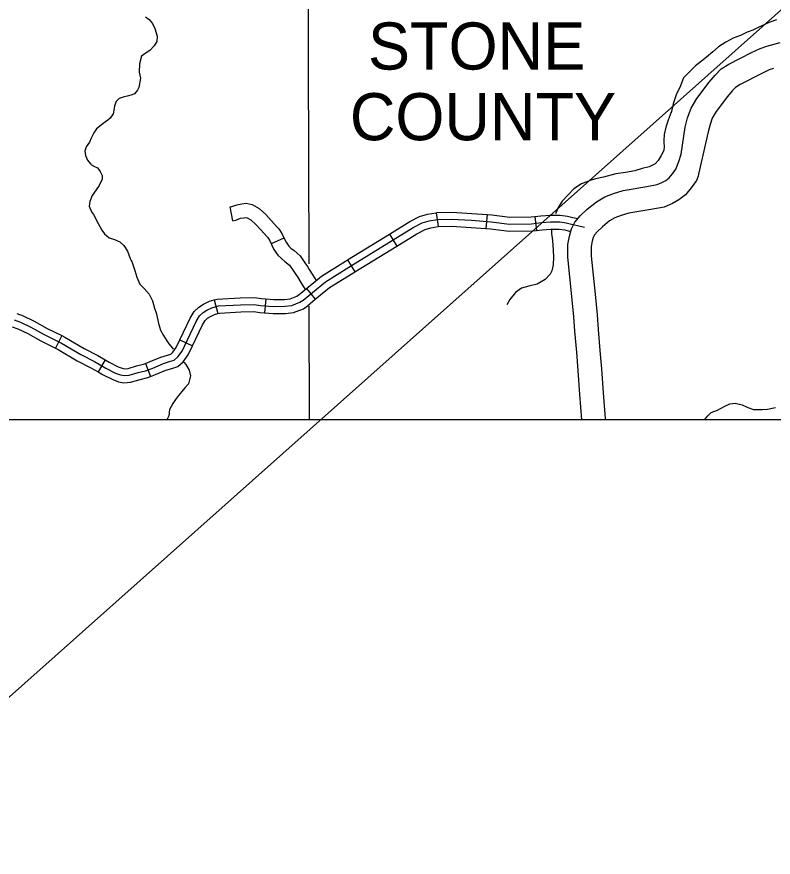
# Model space of a CAD drawing. Extents: x 1377389 to 1380723, y 1168351 to 1170484.
# Drawn here: x 1378518.7 to 1378680.8, y 1168608.3 to 1168788.5 of the extents above; entities that cross this region are included whole.
import ezdxf

# ---------------------------------------------------------------- set-up
doc = ezdxf.new("R2010")
doc.units = 0
for name, color, linetype in [('B_Contour_Elevations', 7, 'Continuous'), ('B_Fill', 7, 'Continuous'), ('B_Text', 7, 'Continuous'), ('Default', 7, 'Continuous')]:
    doc.layers.add(name, color=color, linetype=linetype)

msp = doc.modelspace()

# ---------------------------------------------------------------- linework, layer by layer
at = {"layer": 'B_Contour_Elevations'}
msp.add_line((1378478.5, 1168608.3), (1379068.4, 1169134.14), dxfattribs=at)
at = {"layer": 'B_Fill'}
for p, q in [((1378679.39, 1168782.21), (1378682.25, 1168782.99)), ((1378671.27, 1168778.34), (1378676.1, 1168780.84)), ((1378676.1, 1168780.84), (1378678, 1168781.74)), ((1378678, 1168781.74), (1378679.39, 1168782.21)), ((1378668.29, 1168776.02), (1378669.6, 1168777.34)), ((1378669.6, 1168777.34), (1378671.27, 1168778.34)), ((1378679.89, 1168777.1), (1378678.32, 1168776.36)), ((1378680.85, 1168777.43), (1378679.89, 1168777.1)), ((1378667.02, 1168774.5), (1378668.29, 1168776.02)), ((1378678.32, 1168776.36), (1378673.71, 1168773.97)), ((1378664.42, 1168771), (1378667.02, 1168774.5)), ((1378673.71, 1168773.97), (1378672.7, 1168773.37)), ((1378671.99, 1168772.65), (1378670.95, 1168771.4)), ((1378672.7, 1168773.37), (1378671.99, 1168772.65)), ((1378663.15, 1168768.9), (1378664.42, 1168771)), ((1378670.95, 1168771.4), (1378668.57, 1168768.21)), ((1378662.43, 1168766.87), (1378663.15, 1168768.9)), ((1378668.57, 1168768.21), (1378667.7, 1168766.75)), ((1378658.87, 1168767.95), (1378658.9, 1168768.07)), ((1378661.92, 1168764.84), (1378662.43, 1168766.87)), ((1378667.7, 1168766.75), (1378667.22, 1168765.42)), ((1378661.05, 1168759.03), (1378661.92, 1168764.84)), ((1378667.22, 1168765.42), (1378666.83, 1168763.85)), ((1378666.83, 1168763.85), (1378664.77, 1168754.73)), ((1378659.88, 1168755.84), (1378660.56, 1168757.49)), ((1378660.56, 1168757.49), (1378661.05, 1168759.03)), ((1378659.18, 1168754.83), (1378659.88, 1168755.84)), ((1378657.75, 1168753.44), (1378658.48, 1168753.99)), ((1378658.48, 1168753.99), (1378659.18, 1168754.83)), ((1378664.67, 1168754.34), (1378664.29, 1168753.43)), ((1378664.77, 1168754.73), (1378664.67, 1168754.34)), ((1378648.58, 1168751.28), (1378653.68, 1168752.14)), ((1378653.68, 1168752.14), (1378655.93, 1168752.53)), ((1378655.93, 1168752.53), (1378656.92, 1168752.95)), ((1378656.92, 1168752.95), (1378657.75, 1168753.44)), ((1378664.29, 1168753.43), (1378663.16, 1168751.8)), ((1378644.68, 1168749.91), (1378646.54, 1168750.61)), ((1378646.54, 1168750.61), (1378648.58, 1168751.28)), ((1378661.95, 1168750.36), (1378660.54, 1168749.27)), ((1378663.16, 1168751.8), (1378661.95, 1168750.36)), ((1378640.9, 1168747.28), (1378642.86, 1168748.85)), ((1378642.86, 1168748.85), (1378644.68, 1168749.91)), ((1378659.17, 1168748.48), (1378657.37, 1168747.7)), ((1378660.54, 1168749.27), (1378659.17, 1168748.48)), ((1378564.94, 1168744.79), (1378564.37, 1168747.74)), ((1378608.56, 1168746.49), (1378608.99, 1168743.52)), ((1378639.37, 1168745.86), (1378640.9, 1168747.28)), ((1378654.52, 1168747.21), (1378649.79, 1168746.41)), ((1378657.37, 1168747.7), (1378654.52, 1168747.21)), ((1378619.43, 1168746.11), (1378619.2, 1168743.12)), ((1378629.66, 1168745.68), (1378630.02, 1168742.7)), ((1378638.23, 1168744.47), (1378639.37, 1168745.86)), ((1378645.7, 1168744.72), (1378644.16, 1168743.49)), ((1378646.83, 1168745.38), (1378645.7, 1168744.72)), ((1378648.2, 1168745.89), (1378646.83, 1168745.38)), ((1378649.79, 1168746.41), (1378648.2, 1168745.89)), ((1378637.07, 1168741.49), (1378637.5, 1168743.03)), ((1378637.5, 1168743.03), (1378638.23, 1168744.47)), ((1378644.16, 1168743.49), (1378643.02, 1168742.42)), ((1378575.89, 1168741.07), (1378573.18, 1168739.79)), ((1378598.54, 1168741.9), (1378600.11, 1168739.34)), ((1378636.75, 1168739.67), (1378637.07, 1168741.49)), ((1378642.18, 1168741.2), (1378641.95, 1168740.38)), ((1378642.45, 1168741.73), (1378642.18, 1168741.2)), ((1378643.02, 1168742.42), (1378642.45, 1168741.73)), ((1378636.76, 1168736.93), (1378636.75, 1168739.67)), ((1378641.95, 1168740.38), (1378641.75, 1168739.25)), ((1378641.75, 1168739.25), (1378641.76, 1168737.19)), ((1378589.54, 1168736.37), (1378591.11, 1168733.81)), ((1378637.61, 1168728.52), (1378636.76, 1168736.93)), ((1378641.76, 1168737.19), (1378642.59, 1168729.03)), ((1378580.71, 1168730.23), (1378582.63, 1168727.93)), ((1378638.06, 1168724.2), (1378637.61, 1168728.52)), ((1378642.59, 1168729.03), (1378643.04, 1168724.62)), ((1378560.96, 1168727.79), (1378561.76, 1168724.89)), ((1378571.99, 1168728.02), (1378571.74, 1168725.03)), ((1378638.27, 1168721.1), (1378638.06, 1168724.2)), ((1378643.04, 1168724.62), (1378643.25, 1168721.48)), ((1378643.25, 1168721.48), (1378643.64, 1168716.98)), ((1378528.29, 1168720.16), (1378526.97, 1168717.46)), ((1378638.66, 1168716.56), (1378638.27, 1168721.1)), ((1378553.6, 1168719.25), (1378556.31, 1168717.97)), ((1378638.99, 1168712.66), (1378638.66, 1168716.56)), ((1378643.64, 1168716.98), (1378643.97, 1168713.03)), ((1378537.59, 1168714.95), (1378536.09, 1168712.35)), ((1378546.26, 1168714.19), (1378547.31, 1168711.38)), ((1378639.32, 1168707.55), (1378638.99, 1168712.66)), ((1378643.97, 1168713.03), (1378644.31, 1168707.9)), ((1378639.75, 1168702.1), (1378639.32, 1168707.55)), ((1378644.31, 1168707.9), (1378644.74, 1168702.37)), ((1378644.76, 1168702.1), (1378639.75, 1168702.1)), ((1378644.74, 1168702.37), (1378644.76, 1168702.1))]:
    msp.add_line(p, q, dxfattribs=at)
for points in [[(1378580.94, 1168836.74), (1378581.05, 1168801.57), (1378581.22, 1168735.56)], [(1378546.2, 1168788.52), (1378547, 1168787.96), (1378547.74, 1168787.08), (1378548.24, 1168786.02), (1378548.7, 1168784.32), (1378548.63, 1168783.24), (1378548.11, 1168782.28), (1378547.14, 1168781.3), (1378546.34, 1168780.8), (1378545.4, 1168780.04), (1378544.93, 1168778.4), (1378544.87, 1168776.6), (1378545.16, 1168775.38), (1378544.8, 1168773.36), (1378544.52, 1168772.78), (1378543.91, 1168771.99), (1378543.41, 1168771.75), (1378542.29, 1168771.47), (1378541.42, 1168771.27), (1378540.62, 1168770.99), (1378539.94, 1168770.33), (1378539.56, 1168769.45), (1378539.51, 1168768.83), (1378539.31, 1168767.73), (1378538.69, 1168766.77), (1378538.15, 1168766.35), (1378537.18, 1168765.65), (1378536.34, 1168765.01), (1378535.7, 1168764.45), (1378535.17, 1168763.63), (1378534.57, 1168762.48), (1378534.2, 1168761.64), (1378533.52, 1168760.62), (1378533.22, 1168759.66), (1378533.35, 1168758.78), (1378533.77, 1168757.74), (1378534.45, 1168756.96), (1378534.69, 1168756.78), (1378535.33, 1168756.42), (1378535.91, 1168756.1), (1378536.51, 1168755.36), (1378536.93, 1168754.5), (1378536.91, 1168753.7), (1378536.32, 1168752.3), (1378535.64, 1168751.38), (1378534.83, 1168750.18), (1378534.27, 1168748.9), (1378534.19, 1168747.88), (1378534.68, 1168746.66), (1378535.1, 1168746.08), (1378536.12, 1168744.18), (1378536.84, 1168742.72), (1378537.46, 1168741.94), (1378538.48, 1168741.12), (1378539.6, 1168740.78), (1378540.72, 1168740.22), (1378541.6, 1168739.46), (1378542.38, 1168738.24), (1378542.97, 1168736.66), (1378543.15, 1168736.26), (1378543.27, 1168736.02), (1378543.95, 1168734.08), (1378544.34, 1168732.68), (1378545.04, 1168731.18), (1378545.94, 1168730.24), (1378547, 1168729.02), (1378547.72, 1168727.58), (1378548.13, 1168726.06), (1378548.57, 1168724.82), (1378549.01, 1168722.76), (1378549.48, 1168721.28), (1378550.08, 1168720.2), (1378550.84, 1168719), (1378551.26, 1168718.4), (1378552, 1168717.42), (1378552.19, 1168717.22)], [(1378681.49, 1168787.89), (1378680.07, 1168787.33), (1378677.54, 1168786.24), (1378676.37, 1168785.61), (1378675.17, 1168785.18), (1378673.75, 1168784.47), (1378672.19, 1168783.89), (1378670.58, 1168783.07), (1378669.07, 1168782.05), (1378667.79, 1168781), (1378666.48, 1168779.84), (1378665.37, 1168778.96), (1378664.09, 1168777.97), (1378662.96, 1168776.85), (1378661.54, 1168775.39), (1378660.75, 1168773.36), (1378660.02, 1168771.99), (1378659.35, 1168769.88), (1378658.87, 1168767.95)], [(1378658.9, 1168768.07), (1378658.26, 1168766.37), (1378657.74, 1168764.86), (1378657.4, 1168763.29), (1378657.33, 1168761.96), (1378657.35, 1168761.53), (1378657.36, 1168760.72), (1378657.33, 1168759.81), (1378656.83, 1168758.93), (1378656.74, 1168758.8), (1378656.12, 1168757.67), (1378655.47, 1168757.01), (1378654.16, 1168756.35), (1378652.65, 1168755.96), (1378651.12, 1168755.51), (1378649.11, 1168755.14), (1378647.06, 1168754.81), (1378644.41, 1168754.14), (1378642.69, 1168753.73), (1378641.55, 1168753.39), (1378639.67, 1168752.68), (1378638.05, 1168751.65), (1378636.79, 1168750.32), (1378635.55, 1168748.94), (1378634.7, 1168747.62), (1378634.11, 1168746.27)], [(1378564.37, 1168747.74), (1378564.76, 1168747.81), (1378565.84, 1168748.22), (1378566.91, 1168748.39), (1378567.78, 1168748.51), (1378569.07, 1168748.25), (1378570.58, 1168747.43), (1378572.03, 1168746.1), (1378573.17, 1168744.86), (1378573.91, 1168744.01), (1378574.46, 1168743.4)], [(1378598.54, 1168741.9), (1378602.9, 1168744.58), (1378604.99, 1168745.68), (1378606.69, 1168746.22), (1378608.56, 1168746.49)], [(1378608.56, 1168746.49), (1378608.72, 1168746.51), (1378611.87, 1168746.58), (1378616.2, 1168746.36), (1378619.43, 1168746.11)], [(1378564.94, 1168744.79), (1378565.58, 1168744.91), (1378566.61, 1168745.31), (1378567.34, 1168745.42), (1378567.69, 1168745.47), (1378568.05, 1168745.4), (1378568.83, 1168744.97), (1378569.91, 1168743.98), (1378570.94, 1168742.85), (1378571.67, 1168742.02), (1378572.22, 1168741.4)], [(1378582.01, 1168729.4), (1378584.8, 1168731.68), (1378589.84, 1168734.83), (1378603.63, 1168743.3), (1378605.56, 1168744.32), (1378607.02, 1168744.78), (1378608.84, 1168745.04), (1378611.85, 1168745.1), (1378616.1, 1168744.89), (1378620.3, 1168744.57), (1378624.27, 1168744.07), (1378628.98, 1168744.11), (1378631.09, 1168744.37), (1378633.05, 1168744.52), (1378635.01, 1168744.52), (1378636.4, 1168744.3), (1378637.5, 1168744.02), (1378638.8, 1168743.76), (1378640.34, 1168743.38)], [(1378619.43, 1168746.11), (1378620.44, 1168746.03), (1378624.35, 1168745.54), (1378628.88, 1168745.58), (1378629.66, 1168745.68)], [(1378629.66, 1168745.68), (1378630.95, 1168745.84), (1378633, 1168745.99), (1378635.12, 1168745.99), (1378636.7, 1168745.74), (1378637.83, 1168745.45), (1378638.87, 1168745.25)], [(1378574.46, 1168743.4), (1378574.81, 1168743.01), (1378575.43, 1168742.04), (1378575.93, 1168740.99), (1378576.35, 1168740.15), (1378576.93, 1168739.35), (1378577.35, 1168738.93), (1378578.06, 1168738.37), (1378579.35, 1168737.22), (1378580.36, 1168735.77), (1378580.92, 1168734.94)], [(1378600.11, 1168739.34), (1378604.39, 1168741.97), (1378606.16, 1168742.9), (1378607.36, 1168743.29), (1378608.99, 1168743.52)], [(1378608.96, 1168743.52), (1378611.83, 1168743.58), (1378616.01, 1168743.36), (1378619.2, 1168743.12)], [(1378619.2, 1168743.12), (1378620.14, 1168743.05), (1378624.18, 1168742.54), (1378629.08, 1168742.59), (1378630.02, 1168742.7)], [(1378630.02, 1168742.7), (1378631.24, 1168742.85), (1378633.11, 1168742.99), (1378634.89, 1168742.99), (1378636.1, 1168742.8), (1378637.35, 1168742.48)], [(1378572.22, 1168741.4), (1378572.42, 1168741.19), (1378572.8, 1168740.58), (1378573.23, 1168739.68), (1378573.77, 1168738.59), (1378574.63, 1168737.4), (1378575.36, 1168736.67), (1378576.13, 1168736.07), (1378577.09, 1168735.22), (1378577.89, 1168734.07), (1378578.44, 1168733.25)], [(1378589.54, 1168736.37), (1378598.54, 1168741.9)], [(1378633.28, 1168742.77), (1378633.23, 1168742.04), (1378633.45, 1168740.52), (1378633.63, 1168738.48), (1378633.71, 1168736.99), (1378633.6, 1168735.35), (1378633.31, 1168734.01), (1378632.98, 1168733.34), (1378631.87, 1168732.15), (1378630.21, 1168731.21), (1378628.42, 1168730.78), (1378626.84, 1168730.32), (1378625.52, 1168729.36), (1378624.33, 1168727.92), (1378623.64, 1168726.77)], [(1378591.11, 1168733.81), (1378600.11, 1168739.34)], [(1378580.71, 1168730.23), (1378581.07, 1168730.53), (1378583.94, 1168732.88), (1378589.07, 1168736.08), (1378589.54, 1168736.37)], [(1378580.92, 1168734.94), (1378581.33, 1168734.35), (1378582.08, 1168733.13), (1378582.82, 1168731.96)], [(1378578.44, 1168733.25), (1378578.81, 1168732.72), (1378579.54, 1168731.54), (1378580.48, 1168730.04)], [(1378582.63, 1168727.93), (1378582.98, 1168728.22), (1378585.69, 1168730.44), (1378590.65, 1168733.53), (1378591.11, 1168733.81)], [(1378518.09, 1168723.5), (1378519.43, 1168723.04), (1378521.69, 1168721.96), (1378524.49, 1168720.38), (1378528.25, 1168718.54), (1378532.36, 1168716.1), (1378535.28, 1168714.58), (1378537.74, 1168713.17), (1378539.82, 1168712.11), (1378540.86, 1168711.73), (1378541.7, 1168711.57), (1378542.76, 1168711.65), (1378544.69, 1168712.23), (1378546.25, 1168712.61), (1378547.8, 1168713.19), (1378550.06, 1168714.13), (1378551.41, 1168714.57), (1378552.37, 1168714.9), (1378553.15, 1168715.56), (1378554.08, 1168716.82), (1378557.08, 1168723.18), (1378557.83, 1168724.36), (1378558.59, 1168725.08), (1378559.39, 1168725.6), (1378560.48, 1168726.12), (1378561.86, 1168726.51), (1378566.57, 1168726.75), (1378569.52, 1168726.85), (1378570.9, 1168726.63), (1378573.62, 1168726.41), (1378576.13, 1168726.43), (1378577.59, 1168726.62), (1378579.34, 1168727.28), (1378580.04, 1168727.76), (1378582.01, 1168729.4)], [(1378571.99, 1168728.02), (1378573.67, 1168727.89), (1378576.03, 1168727.91), (1378577.23, 1168728.05), (1378578.65, 1168728.59), (1378579.15, 1168728.93), (1378580.71, 1168730.23)], [(1378553.6, 1168719.25), (1378555.79, 1168723.89), (1378556.69, 1168725.31), (1378557.67, 1168726.24), (1378558.66, 1168726.89), (1378559.97, 1168727.51), (1378560.96, 1168727.79)], [(1378560.96, 1168727.79), (1378561.62, 1168727.97), (1378566.51, 1168728.22), (1378569.61, 1168728.33), (1378571.08, 1168728.09), (1378571.99, 1168728.02)], [(1378571.74, 1168725.03), (1378573.56, 1168724.88), (1378576.23, 1168724.91), (1378577.96, 1168725.12), (1378580.06, 1168725.91), (1378580.96, 1168726.54), (1378582.63, 1168727.93)], [(1378518.65, 1168724.86), (1378519.99, 1168724.4), (1378522.37, 1168723.27), (1378525.17, 1168721.68), (1378528.29, 1168720.16)], [(1378556.31, 1168717.97), (1378558.42, 1168722.44), (1378559.02, 1168723.38), (1378559.54, 1168723.88), (1378560.13, 1168724.27), (1378561.02, 1168724.69), (1378561.76, 1168724.89)], [(1378561.76, 1168724.89), (1378562.1, 1168724.99), (1378566.63, 1168725.22), (1378569.43, 1168725.32), (1378570.72, 1168725.11), (1378571.74, 1168725.03)], [(1378581.25, 1168726.47), (1378581.31, 1168702.1)], [(1378517.68, 1168722.02), (1378518.85, 1168721.62), (1378520.98, 1168720.6), (1378523.78, 1168719.03), (1378526.97, 1168717.46)], [(1378528.29, 1168720.16), (1378528.95, 1168719.84), (1378533.08, 1168717.39), (1378535.99, 1168715.88), (1378537.59, 1168714.95)], [(1378546.26, 1168714.19), (1378547.26, 1168714.56), (1378549.54, 1168715.51), (1378550.95, 1168715.97), (1378551.63, 1168716.2), (1378552.06, 1168716.57), (1378552.81, 1168717.58), (1378553.6, 1168719.25)], [(1378547.31, 1168711.38), (1378548.36, 1168711.77), (1378550.59, 1168712.7), (1378551.89, 1168713.12), (1378553.13, 1168713.54), (1378554.27, 1168714.51), (1378555.4, 1168716.03), (1378556.31, 1168717.97)], [(1378526.97, 1168717.46), (1378527.52, 1168717.2), (1378531.62, 1168714.77), (1378534.55, 1168713.25), (1378536.09, 1168712.35)], [(1378537.59, 1168714.95), (1378538.44, 1168714.46), (1378540.41, 1168713.46), (1378541.25, 1168713.15), (1378541.78, 1168713.05), (1378542.49, 1168713.1), (1378544.3, 1168713.65), (1378545.81, 1168714.02), (1378546.26, 1168714.19)], [(1378554.43, 1168714.55), (1378554.53, 1168714.4), (1378554.87, 1168713.94), (1378555.61, 1168712.76), (1378555.85, 1168711.5), (1378555.46, 1168709.77), (1378554.68, 1168708.95), (1378554.02, 1168708.19), (1378553.33, 1168707.33), (1378552.63, 1168706.43), (1378552.07, 1168705.61), (1378551.4, 1168704.27), (1378551.22, 1168702.91), (1378550.79, 1168702.1)], [(1378536.09, 1168712.35), (1378537.01, 1168711.82), (1378539.21, 1168710.7), (1378540.45, 1168710.25), (1378541.61, 1168710.03), (1378543.04, 1168710.14), (1378545.09, 1168710.75), (1378546.7, 1168711.15), (1378547.31, 1168711.38)], [(1378666.06, 1168702.1), (1378666.06, 1168702.1), (1378666.74, 1168702.94), (1378667.46, 1168703.64), (1378668.85, 1168704.18), (1378670.41, 1168704.98), (1378671.5, 1168705.52), (1378672.62, 1168705.68), (1378674.12, 1168705.28), (1378675.32, 1168704.74), (1378676.56, 1168704.28), (1378678.45, 1168704.29), (1378679.55, 1168704.39), (1378681.27, 1168704.75)]]:
    msp.add_lwpolyline(points, dxfattribs=at)
at = {"layer": 'B_Text'}
msp.add_lwpolyline([(1378340.61, 1169579.43), (1379848.03, 1169579.43), (1379848.03, 1168702.1), (1378340.61, 1168702.1)], close=True, dxfattribs=at)

# ---------------------------------------------------------------- texts
at = {"layer": 'Default'}
for s, p in [('STONE', (1378593.92, 1168777.19)), ('COUNTY', (1378590.03, 1168762.03))]:
    msp.add_text(s, height=10.107, rotation=360, dxfattribs=at).set_placement(p)

doc.saveas('drawing.dxf')
